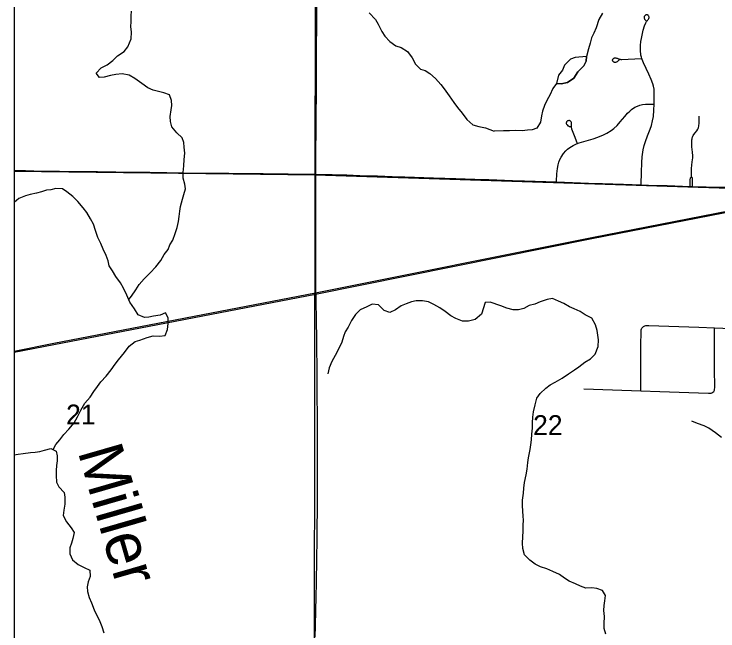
# Model space of a CAD drawing. Extents: x 0 to 34, y 0 to 22.
# Drawn here: x 2.1 to 3.588, y 16.666 to 17.97 of the extents above; entities that cross this region are included whole.
import ezdxf

# ---------------------------------------------------------------- set-up
doc = ezdxf.new("R2010")
doc.units = 0
for name, color, linetype in [('GM_X_Corporation', 7, 'Continuous'), ('GM_X_County_Road', 7, 'Continuous'), ('GM_X_Minor_Lake', 7, 'Continuous'), ('GM_X_Minor_River', 7, 'Continuous'), ('GM_X_Minor_River_Text', 7, 'Continuous'), ('GM_X_Rail_Line', 7, 'Continuous'), ('GM_X_Section_Text', 7, 'Continuous'), ('GM_X_Township_Road', 7, 'Continuous'), ('SH_Data', 7, 'Continuous')]:
    doc.layers.add(name, color=color, linetype=linetype)

msp = doc.modelspace()

# ---------------------------------------------------------------- linework, layer by layer
at = {"layer": 'GM_X_Corporation'}
for points in [[(8.9, 20.9), (2.1, 20.9), (2.1, 14.6217)], [(2.1, 20.6285), (2.1, 14.6217)]]:
    msp.add_lwpolyline(points, dxfattribs=at)
for points in [[(2.1, 18.6502), (2.1, 17.6383), (2.7368, 17.6304), (2.7385, 18.6376)], [(2.7385, 18.6376), (3.7435, 18.6067), (3.7219, 17.5988), (2.7368, 17.6304)], [(2.1, 17.6383), (2.1, 16.6383), (2.7352, 16.6292), (2.7368, 17.6304)], [(2.7368, 17.6304), (3.7219, 17.5988), (3.7247, 16.5938), (2.7352, 16.6292)]]:
    msp.add_lwpolyline(points, close=True, dxfattribs=at)
at = {"layer": 'GM_X_County_Road'}
for points in [[(2.738, 17.6321), (2.738, 17.6584), (2.7382, 17.6821), (2.7385, 17.7225), (2.7389, 17.7504), (2.7391, 17.7703), (2.7393, 17.789), (2.7394, 17.8207), (2.7397, 17.8934), (2.7401, 17.9531), (2.7403, 17.9966)], [(3.4271, 17.8765), (3.4264, 17.879), (3.4256, 17.8838), (3.4249, 17.8938), (3.4247, 17.9037), (3.4253, 17.9124), (3.4264, 17.9191), (3.4304, 17.9361), (3.4332, 17.9456), (3.4356, 17.952), (3.4372, 17.9547), (3.4391, 17.9569), (3.4403, 17.9584), (3.4415, 17.96), (3.4421, 17.9609), (3.4423, 17.9616), (3.4426, 17.9626), (3.4427, 17.9635), (3.4427, 17.9642), (3.4425, 17.9653), (3.4423, 17.966), (3.4417, 17.967), (3.441, 17.9678), (3.4403, 17.9683), (3.4395, 17.9686), (3.4386, 17.9689), (3.4377, 17.969), (3.4367, 17.9688), (3.4359, 17.9685), (3.435, 17.9681), (3.4344, 17.9676), (3.4336, 17.9669), (3.433, 17.9661), (3.4326, 17.9653), (3.4323, 17.9646), (3.4322, 17.9636), (3.4322, 17.9626), (3.4323, 17.9617), (3.4327, 17.9607), (3.4333, 17.9594), (3.4342, 17.9584), (3.4351, 17.9574), (3.436, 17.9567), (3.4372, 17.9559)], [(3.3805, 17.8747), (3.3799, 17.874), (3.3791, 17.873), (3.3782, 17.8721), (3.3774, 17.8713), (3.3766, 17.8707), (3.3758, 17.87), (3.375, 17.8695), (3.3741, 17.869), (3.3728, 17.8685), (3.3718, 17.8683), (3.3708, 17.8682), (3.3699, 17.8683), (3.369, 17.8686), (3.3682, 17.8689), (3.3673, 17.8694), (3.3667, 17.87), (3.3661, 17.8708), (3.3658, 17.8716), (3.3656, 17.8725), (3.3655, 17.8734), (3.3658, 17.8743), (3.3661, 17.8752), (3.3666, 17.876), (3.3672, 17.8766), (3.3681, 17.8771), (3.3689, 17.8775), (3.3699, 17.8778), (3.371, 17.8779), (3.3722, 17.8778), (3.3739, 17.8775), (3.3753, 17.8771), (3.3763, 17.8767), (3.3777, 17.8761), (3.3787, 17.8756), (3.3795, 17.8753), (3.3813, 17.8748), (3.3828, 17.8745), (3.385, 17.8744), (3.426, 17.8764), (3.4271, 17.8765)], [(3.4534, 17.78), (3.4535, 17.7825), (3.4537, 17.803), (3.4532, 17.8117), (3.4523, 17.8178), (3.4509, 17.8226), (3.4473, 17.8319), (3.4419, 17.8437), (3.4307, 17.8673), (3.4278, 17.8742), (3.4271, 17.8765)], [(3.2915, 17.697), (3.295, 17.6983), (3.3244, 17.7065), (3.3343, 17.7099), (3.3464, 17.7148), (3.3536, 17.7185), (3.3625, 17.7241), (3.3679, 17.7283), (3.3752, 17.7351), (3.3819, 17.7424), (3.3914, 17.7539), (3.397, 17.7606), (3.4018, 17.7654), (3.4056, 17.7686), (3.4129, 17.7733), (3.4179, 17.7759), (3.4231, 17.7778), (3.4286, 17.7791), (3.4354, 17.7799), (3.449, 17.78), (3.4534, 17.78)], [(3.4262, 17.6095), (3.4262, 17.611), (3.4268, 17.6351), (3.4274, 17.6568), (3.4284, 17.6686), (3.4304, 17.6834), (3.4324, 17.6925), (3.4348, 17.7008), (3.4394, 17.7131), (3.4451, 17.7269), (3.4478, 17.7351), (3.4502, 17.7448), (3.4518, 17.754), (3.4529, 17.767), (3.4534, 17.78)], [(3.2915, 17.697), (3.291, 17.6982), (3.2853, 17.7129), (3.2796, 17.7267), (3.2792, 17.7285), (3.2789, 17.7298), (3.2787, 17.7318), (3.2788, 17.733), (3.2788, 17.7342), (3.2789, 17.7353), (3.279, 17.7363), (3.279, 17.7377), (3.279, 17.7391), (3.2787, 17.7409), (3.2779, 17.7426), (3.2773, 17.7434), (3.2766, 17.744), (3.2758, 17.7445), (3.275, 17.7449), (3.2741, 17.7451), (3.2732, 17.7453), (3.2713, 17.745), (3.2705, 17.7446), (3.2697, 17.7442), (3.2684, 17.7428), (3.2681, 17.742), (3.2678, 17.7411), (3.2677, 17.7402), (3.2677, 17.7392), (3.2682, 17.7374), (3.2693, 17.7359), (3.2712, 17.7343), (3.272, 17.7338), (3.2729, 17.7333), (3.2739, 17.7328), (3.2753, 17.7325), (3.2764, 17.7324), (3.2772, 17.7324), (3.2783, 17.7326)], [(3.5325, 17.6258), (3.5322, 17.6327), (3.5324, 17.6434), (3.5331, 17.6515), (3.5348, 17.6631), (3.5351, 17.6657), (3.5351, 17.668), (3.5351, 17.6705), (3.5345, 17.6784), (3.5332, 17.6896), (3.5331, 17.6937), (3.533, 17.6972), (3.5333, 17.7047), (3.5336, 17.7065), (3.534, 17.7085), (3.5344, 17.7103), (3.5352, 17.7122), (3.536, 17.7135), (3.5371, 17.7156), (3.5404, 17.7195), (3.5436, 17.7232), (3.5458, 17.7268), (3.5472, 17.7301), (3.5481, 17.7342), (3.5486, 17.7396), (3.5489, 17.7545)], [(3.2466, 17.6156), (3.2467, 17.6171), (3.2475, 17.6324), (3.2488, 17.6442), (3.2502, 17.6515), (3.252, 17.6575), (3.2541, 17.6626), (3.2571, 17.6681), (3.262, 17.6754), (3.2666, 17.6811), (3.2702, 17.6845), (3.2751, 17.6882), (3.2825, 17.6928), (3.2892, 17.6961), (3.2915, 17.697)], [(2.1, 17.6396), (2.1243, 17.6393), (2.1591, 17.6385), (2.1958, 17.6382), (2.2331, 17.6378), (2.2766, 17.6372), (2.3152, 17.6368), (2.363, 17.6362), (2.3873, 17.6359), (2.4227, 17.6354), (2.4563, 17.6349), (2.5539, 17.6337), (2.5837, 17.6333), (2.6266, 17.6331), (2.6795, 17.6328), (2.738, 17.6321)], [(2.7368, 16.6527), (2.7372, 16.6769), (2.738, 16.7099), (2.7386, 16.7372), (2.7392, 16.7683), (2.74, 16.818), (2.7408, 16.8603), (2.7417, 16.9467), (2.7418, 17.0157), (2.7416, 17.0816), (2.7413, 17.1233), (2.7412, 17.1612), (2.7409, 17.2041), (2.7408, 17.2339), (2.7403, 17.2532), (2.74, 17.2836), (2.7397, 17.3222), (2.7391, 17.365), (2.7382, 17.3986), (2.7383, 17.4396), (2.7383, 17.4657), (2.7379, 17.5322), (2.7378, 17.5795), (2.7379, 17.6236), (2.738, 17.6321)], [(2.738, 17.6321), (2.7727, 17.6315), (2.8038, 17.6303), (2.8311, 17.6294), (2.8684, 17.6281), (2.8995, 17.6271), (2.9262, 17.626), (2.987, 17.6241), (3.011, 17.6235), (3.034, 17.6227), (3.0744, 17.6215), (3.1042, 17.6205), (3.1539, 17.6188), (3.1794, 17.6178), (3.2241, 17.6164), (3.2466, 17.6156)], [(3.5293, 17.6061), (3.5344, 17.6059), (3.5633, 17.6049), (3.5863, 17.6043), (3.6068, 17.6043), (3.6197, 17.605), (3.6314, 17.6063), (3.6448, 17.6087), (3.6568, 17.6116), (3.6717, 17.6159), (3.7106, 17.6275), (3.7277, 17.6327), (3.7352, 17.635)], [(3.5293, 17.6061), (3.5293, 17.6069), (3.5298, 17.6214), (3.53, 17.6229), (3.5304, 17.6239), (3.5311, 17.6246), (3.5325, 17.6258)], [(3.5344, 17.6059), (3.5344, 17.6071), (3.5346, 17.6204), (3.5345, 17.6218), (3.5342, 17.6235), (3.5336, 17.6246), (3.5325, 17.6258)], [(3.2466, 17.6156), (3.3148, 17.6132), (3.344, 17.6122), (3.3888, 17.6108), (3.4262, 17.6095)], [(3.4262, 17.6095), (3.4416, 17.6089), (3.4813, 17.6078), (3.5293, 17.6061)]]:
    msp.add_lwpolyline(points, dxfattribs=at)
at = {"layer": 'GM_X_Minor_Lake'}
for points in [[(3.2467, 17.8236), (3.257, 17.823), (3.2699, 17.8254), (3.2837, 17.8346), (3.2923, 17.8481), (3.3047, 17.8608), (3.3095, 17.871), (3.3104, 17.8808)], [(3.3104, 17.8808), (3.2865, 17.8786), (3.2769, 17.8754), (3.2638, 17.8624), (3.2598, 17.8518), (3.2509, 17.8414), (3.2467, 17.8236)]]:
    msp.add_lwpolyline(points, dxfattribs=at)
at = {"layer": 'GM_X_Minor_River'}
for points in [[(2.3426, 17.3665), (2.3486, 17.3741), (2.3573, 17.3871), (2.3644, 17.3983), (2.3754, 17.4106), (2.3878, 17.4232), (2.3999, 17.4358), (2.4101, 17.4492), (2.4173, 17.4619), (2.4255, 17.4727), (2.4296, 17.4825), (2.4355, 17.4926), (2.4404, 17.5065), (2.4449, 17.5193), (2.4479, 17.5318), (2.4493, 17.5427), (2.4507, 17.5537), (2.4521, 17.5635), (2.4559, 17.579), (2.4588, 17.5888), (2.4626, 17.6012), (2.4613, 17.6108), (2.4574, 17.6234), (2.4577, 17.6356), (2.4589, 17.6492), (2.46, 17.6632), (2.4611, 17.6761), (2.4599, 17.689), (2.459, 17.6986), (2.4554, 17.7085), (2.4443, 17.7194), (2.4336, 17.7322), (2.4309, 17.743), (2.4304, 17.754), (2.4323, 17.7676), (2.4337, 17.7774), (2.4328, 17.7877), (2.4289, 17.7996), (2.4165, 17.8041), (2.4056, 17.807), (2.3942, 17.8092), (2.383, 17.8141), (2.3699, 17.8235), (2.3554, 17.8341), (2.3434, 17.8409), (2.3283, 17.8443), (2.3154, 17.8424), (2.3039, 17.8404), (2.2906, 17.8373), (2.2803, 17.8361), (2.2737, 17.8457), (2.2839, 17.8565), (2.2965, 17.863), (2.3089, 17.8722), (2.319, 17.8822), (2.3329, 17.8913), (2.3408, 17.9014), (2.3477, 17.9183), (2.3484, 17.9319), (2.3472, 17.9441), (2.3478, 17.9543), (2.3478, 17.9669), (2.348, 17.9764)], [(2.8508, 17.9729), (2.8645, 17.9589), (2.8699, 17.9492), (2.8775, 17.9338), (2.8841, 17.9234), (2.8944, 17.9121), (2.9075, 17.9031), (2.9184, 17.8994), (2.9318, 17.8914), (2.9421, 17.8782), (2.9486, 17.8648), (2.9593, 17.8539), (2.9691, 17.851), (2.9792, 17.845), (2.9911, 17.8341), (3.0025, 17.8216), (3.0091, 17.812), (3.0198, 17.7976), (3.0296, 17.7833), (3.0374, 17.7732), (3.0477, 17.7612), (3.0572, 17.7473), (3.0698, 17.7363), (3.0826, 17.7326), (3.0971, 17.7301), (3.1151, 17.7227)], [(3.3444, 17.9724), (3.3366, 17.9589), (3.3309, 17.9415), (3.3258, 17.9299), (3.321, 17.9201), (3.3182, 17.9091), (3.3149, 17.8967), (3.3104, 17.8808), (3.3095, 17.871), (3.3047, 17.8608), (3.2923, 17.8481), (3.2837, 17.8346), (3.2699, 17.8254), (3.257, 17.823), (3.2467, 17.8236), (3.239, 17.8127), (3.2326, 17.7992), (3.2271, 17.7894), (3.2216, 17.7774), (3.2176, 17.7649), (3.2155, 17.7551), (3.2133, 17.7419), (3.2055, 17.7295), (3.1956, 17.7259), (3.1853, 17.7246), (3.1747, 17.7236), (3.1606, 17.7243), (3.1477, 17.7234), (3.1349, 17.7237)], [(3.1349, 17.7237), (3.1151, 17.7227)], [(2.1824, 17.0494), (2.1884, 17.06), (2.197, 17.0704), (2.2049, 17.0812), (2.2155, 17.0927), (2.2272, 17.1057), (2.2343, 17.1188), (2.2411, 17.1327), (2.2495, 17.1473), (2.2612, 17.1603), (2.2687, 17.1726), (2.2766, 17.1827), (2.2837, 17.1927), (2.2946, 17.2046), (2.3056, 17.2184), (2.3138, 17.2299), (2.3209, 17.2396), (2.3334, 17.2545), (2.3436, 17.2679), (2.356, 17.2782), (2.3656, 17.281), (2.3813, 17.2866), (2.3943, 17.2897), (2.4072, 17.2894), (2.4194, 17.2906), (2.4242, 17.3034), (2.4257, 17.3159), (2.4256, 17.328), (2.4202, 17.3384), (2.4087, 17.3334), (2.395, 17.3315), (2.3851, 17.3298), (2.3755, 17.3286), (2.3624, 17.3342), (2.3544, 17.347), (2.3449, 17.3613), (2.3384, 17.3762), (2.3316, 17.3905), (2.325, 17.4024), (2.3151, 17.4156), (2.3079, 17.4275), (2.3013, 17.4383), (2.2993, 17.4483), (2.2946, 17.4598), (2.2881, 17.4732), (2.2831, 17.4851), (2.277, 17.4982), (2.2724, 17.5127), (2.2678, 17.5258), (2.2613, 17.5377), (2.2541, 17.5508), (2.246, 17.5605), (2.2345, 17.5741), (2.2242, 17.585), (2.2119, 17.5948), (2.2022, 17.6008), (2.1886, 17.6015), (2.1779, 17.5987), (2.1684, 17.5978), (2.158, 17.5947), (2.1477, 17.5915), (2.134, 17.5888), (2.124, 17.5861), (2.1102, 17.5807), (2.1, 17.5717)], [(3.2624, 17.3587), (3.2515, 17.3635), (3.2387, 17.3691), (3.227, 17.367), (3.2121, 17.3616), (3.2014, 17.3573), (3.1895, 17.3541), (3.178, 17.3478), (3.1666, 17.3447), (3.1552, 17.3449), (3.142, 17.3482), (3.1289, 17.3537), (3.1066, 17.3615)], [(3.1066, 17.3615), (3.0959, 17.3605), (3.0885, 17.3356), (3.0749, 17.3249), (3.0608, 17.3211), (3.0479, 17.3211), (3.0343, 17.3264), (3.0238, 17.332), (3.0112, 17.3414), (3.0004, 17.3489), (2.9876, 17.3564), (2.9764, 17.3617), (2.9636, 17.3643), (2.9503, 17.3639), (2.94, 17.3618), (2.9289, 17.3576), (2.9185, 17.3537), (2.9065, 17.3449), (2.8946, 17.3395), (2.8826, 17.3436), (2.8704, 17.3553), (2.8571, 17.3571), (2.8456, 17.3514), (2.8321, 17.3449), (2.822, 17.3349), (2.8133, 17.3222), (2.8061, 17.308), (2.8002, 17.2982), (2.7969, 17.2885), (2.7928, 17.2768), (2.786, 17.2618), (2.7788, 17.2483), (2.7717, 17.2359), (2.7664, 17.222), (2.7634, 17.21)], [(3.351, 16.6588), (3.3478, 16.671), (3.3476, 16.682), (3.3483, 16.6964), (3.347, 16.7089), (3.348, 16.7195), (3.3489, 16.7294), (3.3503, 16.7411), (3.3444, 16.7515), (3.3323, 16.7555), (3.3218, 16.7569), (3.3089, 16.7567), (3.2979, 16.7607), (3.2874, 16.7659), (3.2739, 16.7711), (3.2638, 16.7777), (3.2533, 16.7851), (3.2394, 16.7918), (3.2262, 16.7974), (3.213, 16.8018), (3.2021, 16.807), (3.1905, 16.8159), (3.179, 16.8268), (3.1755, 16.8401), (3.1753, 16.8519), (3.1759, 16.8652), (3.1762, 16.8769), (3.1768, 16.8902), (3.177, 16.8997), (3.1768, 16.9092), (3.1758, 16.9187), (3.175, 16.932), (3.1752, 16.9426), (3.1773, 16.957), (3.1779, 16.9676), (3.1793, 16.9801), (3.1826, 16.996), (3.1848, 17.0084), (3.1862, 17.0221), (3.1879, 17.0319), (3.1913, 17.0493), (3.1926, 17.0595), (3.1939, 17.0701), (3.1949, 17.0822), (3.1959, 17.0947), (3.1965, 17.1057), (3.1971, 17.1183), (3.1985, 17.1292), (3.2018, 17.144), (3.2055, 17.1579), (3.2125, 17.1684), (3.2241, 17.1796), (3.2337, 17.1862), (3.2441, 17.1921), (3.2586, 17.2006), (3.2721, 17.2098), (3.2848, 17.2183), (3.2944, 17.2245), (3.3067, 17.2342), (3.3186, 17.2415), (3.329, 17.2512), (3.3354, 17.2678), (3.336, 17.2814), (3.3347, 17.2913), (3.3326, 17.3012), (3.3294, 17.3134), (3.3214, 17.3272), (3.3075, 17.3343), (3.297, 17.3414), (3.2842, 17.3473), (3.2744, 17.3513), (3.2624, 17.3587)], [(3.596, 17.0753), (3.5829, 17.085), (3.5694, 17.0948), (3.5589, 17.0999), (3.5454, 17.1043), (3.5329, 17.1095)], [(2.1, 17.0387), (2.109, 17.0397), (2.1193, 17.0409), (2.1349, 17.0435), (2.1448, 17.044), (2.1547, 17.0453), (2.1642, 17.0481), (2.1776, 17.0515), (2.1892, 17.0463), (2.1912, 17.0364), (2.191, 17.0254), (2.1896, 17.0155), (2.1893, 17.0049), (2.1887, 16.9947), (2.1898, 16.9806), (2.1949, 16.9706), (2.2056, 16.9589), (2.2072, 16.949), (2.2072, 16.9342), (2.2054, 16.9217), (2.204, 16.91), (2.2105, 16.8969), (2.2208, 16.8837), (2.227, 16.8741), (2.224, 16.8613), (2.2215, 16.8515), (2.2182, 16.8417), (2.2182, 16.8288), (2.2236, 16.8161), (2.2355, 16.8063), (2.2482, 16.7999)], [(2.2482, 16.7999), (2.2602, 16.7943), (2.261, 16.781), (2.2566, 16.7701), (2.2544, 16.7591), (2.2553, 16.7492), (2.2588, 16.737), (2.2638, 16.7251), (2.2691, 16.7109), (2.2741, 16.6997), (2.2799, 16.6897), (2.2853, 16.6752), (2.2895, 16.6621)]]:
    msp.add_lwpolyline(points, dxfattribs=at)
at = {"layer": 'GM_X_Rail_Line'}
for points in [[(2.1, 17.2578), (2.1839, 17.2743), (2.7373, 17.3807), (3.3215, 17.4979), (3.9612, 17.6228), (4.5554, 17.74), (5.1565, 17.8564), (5.7754, 17.979), (6.3342, 18.0908), (6.9022, 18.2018), (7.3492, 18.2882), (7.4239, 18.3027), (8.0092, 18.4168), (8.4623, 18.5082), (8.9, 18.5958)], [(2.1, 17.2555), (2.1844, 17.272), (2.7377, 17.3784), (3.3219, 17.4956), (3.9616, 17.6205), (4.5558, 17.7377), (5.157, 17.8541), (5.7759, 17.9767), (6.3346, 18.0885), (6.9026, 18.1995), (7.3496, 18.2859), (7.4243, 18.3004), (8.0097, 18.4146), (8.4624, 18.5056), (8.9, 18.5934)]]:
    msp.add_lwpolyline(points, dxfattribs=at)
at = {"layer": 'GM_X_Township_Road'}
for points in [[(2.738, 17.6321), (2.738, 17.6584), (2.7382, 17.6821), (2.7385, 17.7225), (2.7389, 17.7504), (2.7391, 17.7703), (2.7393, 17.789), (2.7394, 17.8207), (2.7397, 17.8934), (2.7401, 17.9531), (2.7403, 17.9966)], [(2.7368, 16.6527), (2.7372, 16.6769), (2.738, 16.7099), (2.7386, 16.7372), (2.7392, 16.7683), (2.74, 16.818), (2.7408, 16.8603), (2.7417, 16.9467), (2.7418, 17.0157), (2.7416, 17.0816), (2.7413, 17.1233), (2.7412, 17.1612), (2.7409, 17.2041), (2.7408, 17.2339), (2.7403, 17.2532), (2.74, 17.2836), (2.7397, 17.3222), (2.7391, 17.365), (2.7382, 17.3986), (2.7383, 17.4396), (2.7383, 17.4657), (2.7379, 17.5322), (2.7378, 17.5795), (2.7379, 17.6236), (2.738, 17.6321)], [(3.4256, 17.1737), (3.4256, 17.1764), (3.4256, 17.2023), (3.4254, 17.2452), (3.4253, 17.2712), (3.4257, 17.2976), (3.4258, 17.2999), (3.4261, 17.3025), (3.4266, 17.3047), (3.4275, 17.3065), (3.4287, 17.3078), (3.4309, 17.3095)], [(3.4309, 17.3095), (3.4336, 17.311), (3.4355, 17.3117), (3.4389, 17.3121), (3.4423, 17.3121), (3.5477, 17.3081), (3.5813, 17.3068)], [(3.5794, 17.172), (3.5807, 17.1748), (3.5813, 17.1772), (3.5816, 17.1801), (3.5815, 17.182), (3.5814, 17.1857), (3.5813, 17.2154), (3.5812, 17.2498), (3.581, 17.2941), (3.5813, 17.3068)], [(3.5813, 17.3068), (3.5987, 17.3061), (3.6347, 17.3047), (3.6632, 17.3034), (3.7299, 17.3017), (3.732, 17.3017)], [(3.3047, 17.1781), (3.3255, 17.1773), (3.4256, 17.1737)], [(3.4256, 17.1737), (3.4651, 17.1721), (3.547, 17.1695), (3.5681, 17.1689), (3.5699, 17.1688), (3.5722, 17.1688), (3.5739, 17.1691), (3.5754, 17.1697), (3.5772, 17.1706), (3.5794, 17.172)]]:
    msp.add_lwpolyline(points, dxfattribs=at)
at = {"layer": 'SH_Data'}
msp.add_line((2.1, 20.9), (2.1, 14.1), dxfattribs=at)

# ---------------------------------------------------------------- texts
at = {"layer": 'GM_X_Minor_River_Text'}
msp.add_text('Miller', height=0.09476, rotation=286.0959, dxfattribs=at).set_placement((2.2341, 17.0457))
at = {"layer": 'GM_X_Section_Text'}
for s, p in [('21', (2.21, 17.1028)), ('22', (3.1975, 17.0803))]:
    msp.add_text(s, height=0.04186, rotation=0, dxfattribs=at).set_placement(p)

doc.saveas('drawing.dxf')
